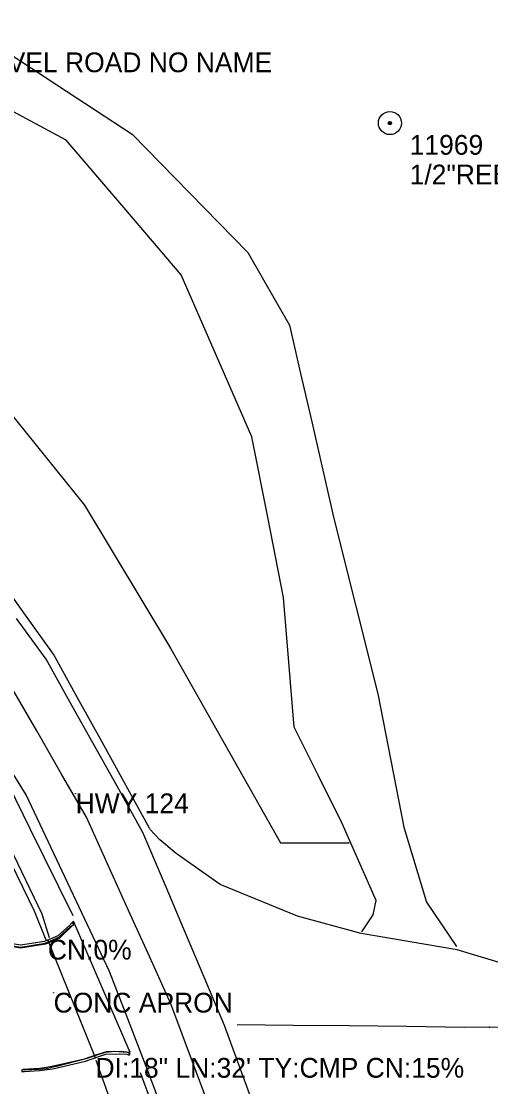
# Model space of a CAD drawing. Extents: x 1050807 to 1053552, y 395828 to 398415.
# Drawn here: x 1052037.5 to 1052156.1, y 397799.4 to 398068.8 of the extents above; entities that cross this region are included whole.
import ezdxf

# ---------------------------------------------------------------- set-up
doc = ezdxf.new("R2010")
doc.units = 0
for name, color, linetype in [('S_CROSS_DRAIN', 7, 'Continuous'), ('S_CROSS_DRAIN_ANNOT', 7, 'Continuous'), ('S_CURB', 7, 'Continuous'), ('S_DITCHLINE', 7, 'Continuous'), ('S_DRG_PT_SYM', 7, 'Continuous'), ('S_EDGE_CONCRETE', 7, 'Continuous'), ('S_EDGE_PAVEMENT', 7, 'Continuous'), ('S_GRAVEL_ROAD', 7, 'Continuous'), ('S_IRON_PIN', 7, 'Continuous'), ('S_IRON_PIN_ANNOT', 7, 'Continuous'), ('S_MSC_PT_SYM', 7, 'Continuous'), ('S_PAVEMENT_CROWN', 7, 'Continuous'), ('S_SHOULDER', 7, 'Continuous'), ('S_SURVEY_TEXT_ANNOT', 7, 'Continuous'), ('S_UTL_PT_SYM', 7, 'Continuous'), ('S_WATER_UTILITIES', 7, 'Continuous')]:
    doc.layers.add(name, color=color, linetype=linetype)

msp = doc.modelspace()

# ---------------------------------------------------------------- linework, layer by layer
at = {"layer": 'S_CROSS_DRAIN'}
msp.add_line((1052056.2, 397806.68), (1052044.17, 397836.55), dxfattribs=at)
at = {"layer": 'S_CURB'}
for points in [[(1052050.31, 397840.95), (1052049.6, 397840.16), (1052046.66, 397837.56), (1052043.32, 397836.12), (1052037.27, 397835.2), (1052030.49, 397836.28), (1052026.08, 397837.6), (1052025.26, 397837.75), (1052025.2, 397837.4), (1052025.95, 397837.16), (1052030.36, 397835.85), (1052037.25, 397834.67), (1052043.52, 397835.7), (1052046.94, 397837.22), (1052049.93, 397839.91), (1052050.76, 397840.38), (1052050.38, 397840.93)], [(1052050.19, 397839.99), (1052047.1, 397836.98), (1052043.53, 397835.43), (1052037.22, 397834.47), (1052030.38, 397835.68), (1052025.31, 397837.34)], [(1052037.49, 397803.23), (1052038.23, 397803.27), (1052042.05, 397803.47), (1052045.43, 397803.96), (1052053.69, 397805.87), (1052056.26, 397806.79), (1052058.84, 397807.61), (1052062.27, 397807.69), (1052064.12, 397807.6), (1052064.8, 397807.36), (1052064.72, 397807.97), (1052064.18, 397808.04), (1052061.06, 397808.27), (1052058.68, 397808.02), (1052056.26, 397807.3), (1052053.76, 397806.43), (1052046.23, 397804.51), (1052043.7, 397803.96), (1052041.94, 397803.78), (1052038.19, 397803.59), (1052037.6, 397803.66), (1052037.61, 397803.3)], [(1052037.83, 397803.84), (1052042.15, 397804.1), (1052043.79, 397804.35), (1052045.57, 397804.72), (1052053.43, 397806.49), (1052056.33, 397807.45), (1052059.06, 397808.32), (1052062.8, 397808.36), (1052064.61, 397808.1)]]:
    msp.add_lwpolyline(points, dxfattribs=at)
at = {"layer": 'S_DITCHLINE'}
for points in [[(1052044.57, 397837.02), (1052042.71, 397843.02), (1052034.56, 397860.05), (1052026.4, 397877.08), (1052014.15, 397896.07), (1052001.9, 397915.06), (1051993.3, 397924.87), (1051984.69, 397934.68), (1051976.08, 397944.49), (1051967.48, 397954.3), (1051953.82, 397966.69), (1051940.17, 397979.07), (1051928.17, 397988.62), (1051927.23, 397987.62), (1051944.65, 397973.64), (1051959.58, 397959.55), (1051974.51, 397945.46), (1051988.4, 397928.84), (1052002.28, 397912.21), (1052012.59, 397896.28), (1052022.89, 397880.34), (1052031.8, 397862.09), (1052040.71, 397843.83), (1052043.64, 397836.55)], [(1052106.17, 397668.06), (1052103.97, 397676.24), (1052097.83, 397691.75), (1052091.69, 397707.25), (1052084.99, 397725.46), (1052078.3, 397743.68), (1052071.74, 397761.24), (1052065.18, 397778.8), (1052060.21, 397795.41), (1052056.36, 397805.99)]]:
    msp.add_lwpolyline(points, dxfattribs=at)
at = {"layer": 'S_DRG_PT_SYM'}
for points in [[(1052044.17, 397836.55), (1052044.17, 397836.6), (1052044.17, 397836.55), (1052044.12, 397836.55), (1052044.17, 397836.55), (1052044.17, 397836.5), (1052044.17, 397836.55), (1052044.22, 397836.55)], [(1052056.2, 397806.68), (1052056.2, 397806.73), (1052056.2, 397806.68), (1052056.15, 397806.68), (1052056.2, 397806.68), (1052056.2, 397806.63), (1052056.2, 397806.68), (1052056.25, 397806.68)]]:
    msp.add_lwpolyline(points, dxfattribs=at)
at = {"layer": 'S_EDGE_CONCRETE'}
msp.add_lwpolyline([(1052064.83, 397807.47), (1052064.94, 397808.02), (1052057.78, 397824.64), (1052050.62, 397841.26), (1052050.35, 397840.94)], dxfattribs=at)
at = {"layer": 'S_EDGE_PAVEMENT'}
for points in [[(1052095.71, 397795.99), (1052088.82, 397814.85), (1052083.67, 397827.06), (1052078.51, 397839.26), (1052073.36, 397851.46), (1052068.2, 397863.67), (1052062.08, 397874.62), (1052055.95, 397885.57), (1052049.82, 397896.53), (1052043.7, 397907.48), (1052036.23, 397917.81)], [(1052073.59, 397792.48), (1052068.98, 397804.51), (1052064.36, 397816.53), (1052059.74, 397828.56), (1052049.22, 397850.87), (1052038.69, 397873.19), (1052032.04, 397883.85)], [(1052166.06, 397828.48), (1052147.64, 397834.05), (1052123.38, 397838.16), (1052107.28, 397842.53), (1052087.72, 397850.56), (1052076.6, 397858.39), (1052072.48, 397861.84), (1052069.97, 397864.51)]]:
    msp.add_lwpolyline(points, dxfattribs=at)
at = {"layer": 'S_GRAVEL_ROAD'}
for points in [[(1051941.6, 398111.76), (1051957.6, 398097.06), (1051970.21, 398085.36), (1051984.67, 398078.88), (1052006.03, 398072.02), (1052027.38, 398065.17), (1052046.41, 398052.69), (1052065.44, 398040.21), (1052080.08, 398025.28), (1052094.72, 398010.35), (1052105.27, 397991.93), (1052108.07, 397979.7), (1052110.87, 397967.48), (1052113.67, 397955.25), (1052116.48, 397943.02), (1052122.03, 397920.87), (1052127.57, 397898.72), (1052130.86, 397881.88), (1052134.15, 397865.05), (1052139.91, 397846.05), (1052147.47, 397834.83)], [(1052123.52, 397838.53), (1052126.37, 397842.85), (1052127.19, 397846.52), (1052118.6, 397865.94), (1052112.52, 397878.14), (1052106.44, 397890.34), (1052105.1, 397906.73), (1052103.75, 397923.13), (1052099.75, 397943.42), (1052095.74, 397963.72), (1052086.81, 397984.21), (1052077.87, 398004.7), (1052063.35, 398021.7), (1052048.82, 398038.69), (1052033.31, 398047.09), (1052017.79, 398055.49), (1051999.69, 398060.95), (1051981.6, 398066.41), (1051966.31, 398066.83), (1051951.02, 398067.25), (1051929.14, 398062.88)]]:
    msp.add_lwpolyline(points, dxfattribs=at)
at = {"layer": 'S_IRON_PIN'}
for radius in [2.91, 0.411, 0.262, 0.212, 0.145, 0.0822, 0.0581]:
    msp.add_circle((1052130.63, 398043.03), radius, dxfattribs=at)
at = {"layer": 'S_MSC_PT_SYM'}
for points in [[(1052051.19, 397873.55), (1052051.19, 397873.6), (1052051.19, 397873.55), (1052051.14, 397873.55), (1052051.19, 397873.55), (1052051.19, 397873.5), (1052051.19, 397873.55), (1052051.24, 397873.55)], [(1052045.61, 397823.15), (1052045.61, 397823.2), (1052045.61, 397823.15), (1052045.56, 397823.15), (1052045.61, 397823.15), (1052045.61, 397823.1), (1052045.61, 397823.15), (1052045.66, 397823.15)], [(1052155.81, 397814.47), (1052155.81, 397814.52), (1052155.81, 397814.47), (1052155.76, 397814.47), (1052155.81, 397814.47), (1052155.81, 397814.42), (1052155.81, 397814.47), (1052155.86, 397814.47)]]:
    msp.add_lwpolyline(points, dxfattribs=at)
at = {"layer": 'S_PAVEMENT_CROWN'}
for points in [[(1052092.01, 397815.11), (1052106.18, 397815), (1052120.36, 397814.9), (1052134.89, 397814.68), (1052149.41, 397814.47), (1052168.73, 397814.57), (1052188.05, 397814.67), (1052206.43, 397815.88), (1052224.82, 397817.09), (1052245.96, 397820.35), (1052267.11, 397823.61), (1052287.9, 397829.23), (1052308.68, 397834.85), (1052331.73, 397843.05), (1052354.77, 397851.25), (1052376.28, 397859.51), (1052397.79, 397867.77), (1052417.71, 397876.32), (1052437.63, 397884.87), (1052456.35, 397894.03), (1052475.08, 397903.2), (1052491.75, 397913.53), (1052508.43, 397923.86)], [(1052083.81, 397797.39), (1052075.25, 397820.32), (1052069.92, 397832.12), (1052064.58, 397843.93), (1052059.25, 397855.73), (1052053.92, 397867.54), (1052047.64, 397878.45), (1052041.36, 397889.37), (1052035.08, 397900.29)]]:
    msp.add_lwpolyline(points, dxfattribs=at)
at = {"layer": 'S_SHOULDER'}
for points in [[(1052069.97, 397864.61), (1052063.87, 397875.65), (1052057.77, 397886.69), (1052051.67, 397897.73), (1052045.57, 397908.78), (1052038.12, 397919.18), (1052030.67, 397929.57), (1052023.22, 397939.97), (1052015.78, 397950.37), (1052006.78, 397959.81), (1051997.77, 397969.24), (1051988.77, 397978.67), (1051979.77, 397988.1), (1051962.15, 398002.23), (1051944.53, 398016.35), (1051934.5, 398023.11)], [(1052050.55, 397842.58), (1052039.7, 397864.61), (1052028.85, 397886.64), (1052021.35, 397897.42), (1052013.86, 397908.2), (1052006.37, 397918.98), (1051998.87, 397929.76), (1051981.88, 397947.71), (1051964.88, 397965.66), (1051950.67, 397977.79), (1051936.46, 397989.93), (1051922.29, 398000.29)], [(1052114.06, 397674.75), (1052106.02, 397697.65), (1052097.99, 397720.54), (1052093.51, 397732.69), (1052089.03, 397744.85), (1052084.54, 397757), (1052080.06, 397769.15), (1052073.84, 397786.05), (1052067.62, 397802.95)]]:
    msp.add_lwpolyline(points, dxfattribs=at)
at = {"layer": 'S_UTL_PT_SYM'}
for points in [[(1052053.44, 397946.43), (1052053.44, 397946.48), (1052053.44, 397946.43), (1052053.39, 397946.43), (1052053.44, 397946.43), (1052053.44, 397946.38), (1052053.44, 397946.43), (1052053.49, 397946.43)], [(1052075.21, 397910.28), (1052075.21, 397910.33), (1052075.21, 397910.28), (1052075.16, 397910.28), (1052075.21, 397910.28), (1052075.21, 397910.23), (1052075.21, 397910.28), (1052075.26, 397910.28)], [(1052102.99, 397861.04), (1052102.99, 397861.09), (1052102.99, 397861.04), (1052102.94, 397861.04), (1052102.99, 397861.04), (1052102.99, 397860.99), (1052102.99, 397861.04), (1052103.04, 397861.04)], [(1052120.23, 397861.05), (1052120.23, 397861.1), (1052120.23, 397861.05), (1052120.18, 397861.05), (1052120.23, 397861.05), (1052120.23, 397861), (1052120.23, 397861.05), (1052120.28, 397861.05)], [(1052155.81, 397814.47), (1052155.81, 397814.52), (1052155.81, 397814.47), (1052155.76, 397814.47), (1052155.81, 397814.47), (1052155.81, 397814.42), (1052155.81, 397814.47), (1052155.86, 397814.47)]]:
    msp.add_lwpolyline(points, dxfattribs=at)
at = {"layer": 'S_WATER_UTILITIES'}
for p, q in [((1052018.98, 397989.06), (1052053.44, 397946.43)), ((1052053.44, 397946.43), (1052075.21, 397910.28)), ((1052075.21, 397910.28), (1052102.99, 397861.04)), ((1052102.99, 397861.04), (1052120.23, 397861.05))]:
    msp.add_line(p, q, dxfattribs=at)

# ---------------------------------------------------------------- texts
at = {"layer": 'S_CROSS_DRAIN_ANNOT'}
for s, p in [('CN:0%', (1052044.17, 397831.55)), ('DI:18" LN:32\' TY:CMP CN:15%', (1052056.2, 397801.68))]:
    msp.add_text(s, height=5, dxfattribs=at).set_placement(p)
at = {"layer": 'S_IRON_PIN_ANNOT'}
for s, p in [('11969', (1052135.63, 398035.03)), ('1/2"REBAR PLS1378 GARZA', (1052135.63, 398027.53))]:
    msp.add_text(s, height=5, dxfattribs=at).set_placement(p)
at = {"layer": 'S_SURVEY_TEXT_ANNOT'}
for s, p in [('GRAVEL ROAD NO NAME', (1052019.52, 398055.89)), ('HWY 124', (1052051.19, 397868.55)), ('CONC APRON', (1052045.61, 397818.15))]:
    msp.add_text(s, height=5, dxfattribs=at).set_placement(p)

doc.saveas('drawing.dxf')
